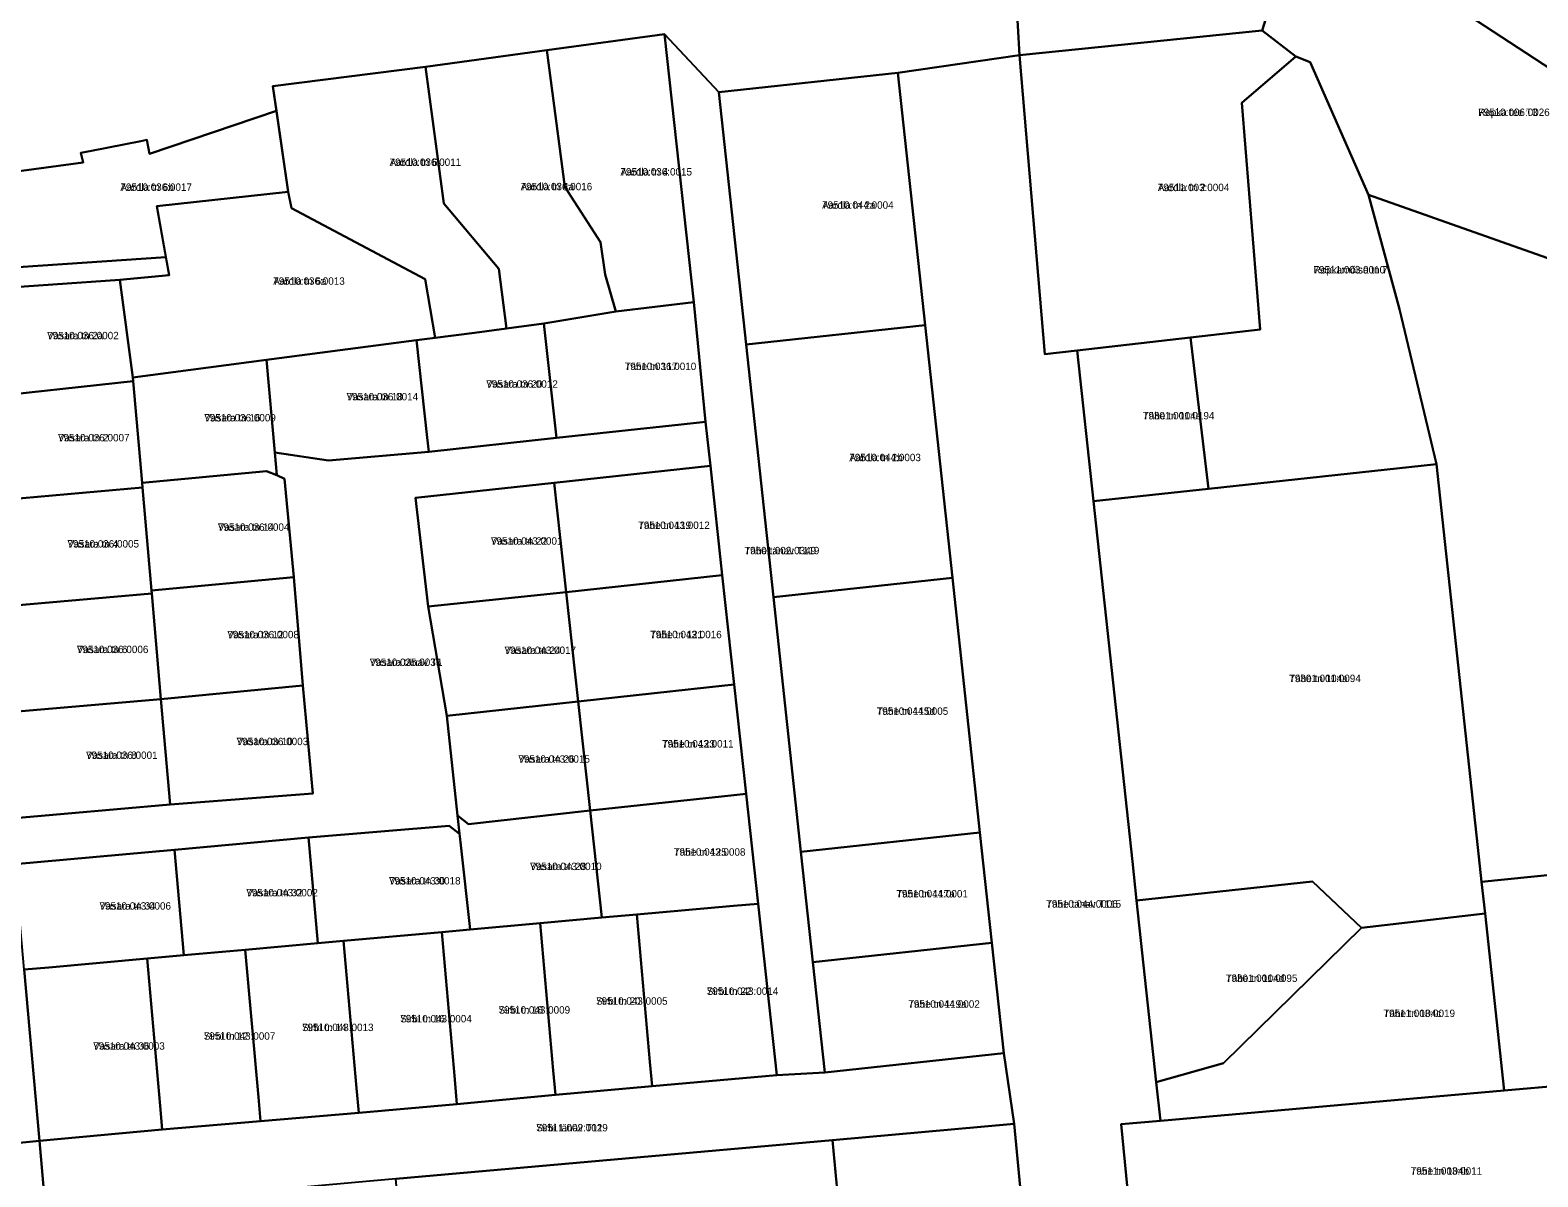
# Model space of a CAD drawing. Extents: x 643847 to 663718, y 6468443 to 6482775.
# Drawn here: x 659596.7 to 659902.3, y 6471374.4 to 6471607 of the extents above; entities that cross this region are included whole.
import ezdxf

# ---------------------------------------------------------------- set-up
doc = ezdxf.new("R2010")
doc.units = 0
for name, color, linetype in [('L_AADRESS', 7, 'Continuous'), ('PIIR', 7, 'Continuous'), ('TUNNUS', 7, 'Continuous')]:
    doc.layers.add(name, color=color, linetype=linetype)

msp = doc.modelspace()

# ---------------------------------------------------------------- linework, layer by layer
at = {"layer": 'PIIR'}
for points in [[(659817.75, 6471799.3), (659833.61, 6471792.85), (659837.53, 6471744.15), (659838.53, 6471692.21), (659839.36, 6471674.7), (659855.96, 6471637.45), (659846.41, 6471606.89), (659797.25, 6471601.92), (659795.21, 6471637.67), (659796.11, 6471658.09), (659796.4, 6471678.1), (659798.71, 6471689.75), (659806.62, 6471693.9), (659821.29, 6471696.22), (659821.65, 6471730.04), (659821.63, 6471758.67), (659819.49, 6471779.17)], [(659795.21, 6471637.67), (659797.25, 6471601.92), (659772.6, 6471598.32), (659736.31, 6471594.4), (659725.24, 6471606.19), (659701.45, 6471602.91), (659676.82, 6471599.52), (659645.89, 6471595.59), (659646.6, 6471590.65), (659620.87, 6471581.91), (659620.31, 6471584.76), (659619.1, 6471584.49), (659609.15, 6471582.53), (659606.98, 6471582.1), (659607.41, 6471580.11), (659580.87, 6471576.54), (659578.73, 6471609.63), (659626.74, 6471615.64), (659641.98, 6471617.51), (659647.44, 6471618.38), (659677.48, 6471622.19), (659712.15, 6471626.9), (659754.93, 6471632.45)], [(659846.41, 6471606.89), (659855.96, 6471637.45), (659873.19, 6471619.88), (659930.09, 6471582.62), (659950.05, 6471577.2), (659951.45, 6471565.89), (659966.86, 6471567.85), (659964.82, 6471541.72), (659932.46, 6471550.82), (659867.98, 6471573.55), (659856.17, 6471600.52), (659853.27, 6471601.63)], [(659701.45, 6471602.91), (659725.24, 6471606.19), (659731.24, 6471551.82), (659715.43, 6471549.92), (659713.23, 6471557.45), (659712.33, 6471563.99), (659705.05, 6471575.23)], [(659734.57, 6471518.62), (659733.58, 6471527.55), (659731.24, 6471551.82), (659725.24, 6471606.19), (659736.31, 6471594.4), (659741.84, 6471543.2), (659747.35, 6471492), (659752.93, 6471440.3), (659755.34, 6471417.93), (659757.75, 6471395.56), (659748.04, 6471395.02), (659744.24, 6471429.79), (659741.81, 6471452.1), (659739.38, 6471474.28), (659736.98, 6471496.45)], [(659846.41, 6471606.89), (659853.27, 6471601.63), (659842.32, 6471592.24), (659846.03, 6471546.27), (659831.88, 6471544.66), (659808.92, 6471542.03), (659802.39, 6471541.28), (659797.25, 6471601.92)], [(659676.82, 6471599.52), (659701.45, 6471602.91), (659705.05, 6471575.23), (659712.33, 6471563.99), (659713.23, 6471557.45), (659715.43, 6471549.92), (659700.8, 6471547.47), (659693.23, 6471546.47), (659691.66, 6471558.56), (659680.51, 6471571.8)], [(659772.6, 6471598.32), (659797.25, 6471601.92), (659802.39, 6471541.28), (659808.92, 6471542.03), (659812.22, 6471511.45), (659820.11, 6471438.38), (659820.96, 6471430.45), (659824.96, 6471393.57), (659825.8, 6471385.79), (659817.82, 6471385.09), (659820.85, 6471354.53), (659824.14, 6471354.79), (659832.72, 6471264.56), (659807.79, 6471262.68), (659803.98, 6471302.78), (659796.16, 6471385.13), (659794.04, 6471399.48), (659791.63, 6471421.84), (659789.22, 6471444.21), (659783.64, 6471495.91), (659778.13, 6471547.12)], [(659856.17, 6471600.52), (659867.98, 6471573.55), (659874.28, 6471550.37), (659881.79, 6471518.95), (659835.58, 6471513.95), (659831.88, 6471544.66), (659846.03, 6471546.27), (659842.32, 6471592.24), (659853.27, 6471601.63)], [(659676.82, 6471599.52), (659680.51, 6471571.8), (659691.66, 6471558.56), (659693.23, 6471546.47), (659686.76, 6471545.62), (659678.76, 6471544.58), (659676.73, 6471556.49), (659649.67, 6471570.9), (659648.96, 6471574.16), (659645.89, 6471595.59)], [(659772.6, 6471598.32), (659778.13, 6471547.12), (659741.84, 6471543.2), (659736.31, 6471594.4)], [(659580.87, 6471576.54), (659607.41, 6471580.11), (659606.98, 6471582.1), (659609.15, 6471582.53), (659619.1, 6471584.49), (659620.31, 6471584.76), (659620.87, 6471581.91), (659646.6, 6471590.65), (659648.96, 6471574.16), (659622.36, 6471571.31), (659624.2, 6471560.96), (659582.22, 6471558.13)], [(659965.79, 6471536.9), (660010.65, 6471539.18), (660217.02, 6471561.69), (660296.35, 6471571.17), (660384.16, 6471579.66), (660385.88, 6471550.23), (660391.97, 6471445.42), (660297.43, 6471441.39), (660298.21, 6471426.96), (660277.53, 6471425.24), (660188.47, 6471417.61), (660128.45, 6471412.44), (659932.57, 6471395.15), (659895.48, 6471391.93), (659891.61, 6471427.79), (659890.91, 6471434.24), (659966.88, 6471441.96), (659984.79, 6471443.78)], [(659648.96, 6471574.16), (659649.67, 6471570.9), (659676.73, 6471556.49), (659678.76, 6471544.58), (659674.99, 6471544.08), (659647.16, 6471540.43), (659644.61, 6471540.1), (659617.49, 6471536.51), (659614.86, 6471556.32), (659624.85, 6471557.31), (659622.36, 6471571.31)], [(659984.79, 6471443.78), (659966.88, 6471441.96), (659890.91, 6471434.24), (659890.36, 6471439.34), (659884.22, 6471496.37), (659881.79, 6471518.95), (659874.28, 6471550.37), (659867.98, 6471573.55), (659932.46, 6471550.82), (659964.82, 6471541.72), (659965.79, 6471536.9)], [(659582.62, 6471554.14), (659587.61, 6471554.48), (659614.86, 6471556.32), (659617.49, 6471536.51), (659617.55, 6471535.79), (659585.24, 6471532.27)], [(659733.59, 6471527.57), (659728.62, 6471527.02), (659703.38, 6471524.27), (659700.8, 6471547.47), (659715.43, 6471549.92), (659731.24, 6471551.82)], [(659677.49, 6471521.46), (659677.16, 6471524.36), (659674.99, 6471544.08), (659678.76, 6471544.58), (659686.76, 6471545.62), (659693.23, 6471546.47), (659700.8, 6471547.47), (659703.38, 6471524.27)], [(659783.64, 6471495.91), (659747.35, 6471492), (659741.84, 6471543.2), (659778.13, 6471547.12)], [(659657.15, 6471519.7), (659646.26, 6471521.32), (659644.61, 6471540.1), (659647.16, 6471540.43), (659674.99, 6471544.08), (659677.16, 6471524.36), (659677.49, 6471521.46)], [(659808.92, 6471542.03), (659831.88, 6471544.66), (659835.58, 6471513.95), (659812.22, 6471511.45)], [(659646.66, 6471516.7), (659644.6, 6471517.52), (659619.37, 6471515.15), (659617.55, 6471535.79), (659617.49, 6471536.51), (659644.61, 6471540.1), (659646.26, 6471521.32)], [(659585.24, 6471532.27), (659617.55, 6471535.79), (659619.37, 6471515.15), (659619.46, 6471514.22), (659592.06, 6471511.8), (659587.13, 6471511.37)], [(659820.11, 6471438.38), (659812.22, 6471511.45), (659835.58, 6471513.95), (659881.79, 6471518.95), (659884.22, 6471496.37), (659890.36, 6471439.34), (659890.91, 6471434.24), (659891.62, 6471427.83), (659866.56, 6471424.91), (659856.64, 6471434.3), (659820.96, 6471430.45)], [(659619.46, 6471514.22), (659619.37, 6471515.15), (659644.6, 6471517.52), (659646.66, 6471516.7), (659648.25, 6471516), (659650.14, 6471496.01), (659621.3, 6471493.35)], [(659736.98, 6471496.45), (659705.35, 6471493), (659702.92, 6471515.17), (659734.57, 6471518.62)], [(659587.13, 6471511.37), (659592.06, 6471511.8), (659619.46, 6471514.22), (659621.3, 6471493.35), (659621.36, 6471492.73), (659593.58, 6471490.27), (659589.07, 6471489.87)], [(659705.35, 6471493), (659677.34, 6471490.06), (659674.78, 6471512.13), (659702.92, 6471515.17)], [(659621.36, 6471492.73), (659621.3, 6471493.35), (659650.14, 6471496.01), (659651.98, 6471474.03), (659623.19, 6471471.27)], [(659739.38, 6471474.28), (659734.42, 6471473.74), (659707.76, 6471470.84), (659705.35, 6471493), (659736.98, 6471496.45)], [(659789.22, 6471444.21), (659752.93, 6471440.3), (659747.35, 6471492), (659783.64, 6471495.91)], [(659589.07, 6471489.87), (659593.58, 6471490.27), (659621.36, 6471492.73), (659623.19, 6471471.27), (659591, 6471468.53)], [(659677.34, 6471490.06), (659705.35, 6471493), (659707.76, 6471470.84), (659681.12, 6471467.92)], [(659651.98, 6471474.03), (659653.98, 6471452.14), (659625.04, 6471449.9), (659623.19, 6471471.27)], [(659741.81, 6471452.1), (659736.84, 6471451.56), (659710.19, 6471448.68), (659707.76, 6471470.84), (659734.42, 6471473.74), (659739.38, 6471474.28)], [(659591, 6471468.53), (659623.19, 6471471.27), (659625.04, 6471449.9), (659592.86, 6471447.07)], [(659683.34, 6471447.72), (659681.12, 6471467.92), (659707.76, 6471470.84), (659710.19, 6471448.68), (659685.54, 6471445.95)], [(659744.24, 6471429.79), (659739.26, 6471429.35), (659719.64, 6471427.6), (659712.56, 6471426.97), (659710.19, 6471448.68), (659736.84, 6471451.56), (659741.81, 6471452.1)], [(659684, 6471441.7), (659683.34, 6471447.72), (659685.54, 6471445.95), (659710.19, 6471448.68), (659712.56, 6471426.97), (659700.05, 6471425.84), (659685.88, 6471424.56)], [(659681.59, 6471445.6), (659683.75, 6471443.94), (659684, 6471441.7), (659685.88, 6471424.56), (659680.14, 6471424.05), (659660.22, 6471422.27), (659655.03, 6471421.8), (659653.34, 6471440.98), (659653.14, 6471443.22)], [(659653.14, 6471443.22), (659653.34, 6471440.98), (659655.03, 6471421.8), (659640.3, 6471420.47), (659627.86, 6471419.35), (659625.96, 6471440.76)], [(659755.34, 6471417.93), (659752.93, 6471440.3), (659789.22, 6471444.21), (659791.63, 6471421.84)], [(659625.96, 6471440.76), (659627.86, 6471419.35), (659620.39, 6471418.67), (659600.46, 6471416.88), (659595.49, 6471416.44), (659593.6, 6471437.84)], [(659824.96, 6471393.57), (659820.96, 6471430.45), (659856.64, 6471434.3), (659866.56, 6471424.91), (659838.61, 6471397.43)], [(659703.15, 6471391.01), (659702.71, 6471395.98), (659700.05, 6471425.84), (659712.56, 6471426.97), (659719.64, 6471427.6), (659722.3, 6471397.74), (659722.75, 6471392.76)], [(659722.75, 6471392.76), (659722.3, 6471397.74), (659719.64, 6471427.6), (659739.26, 6471429.35), (659744.24, 6471429.79), (659748.04, 6471395.02)], [(659825.8, 6471385.79), (659824.96, 6471393.57), (659838.61, 6471397.43), (659866.56, 6471424.91), (659891.62, 6471427.83), (659895.48, 6471391.93), (659857.14, 6471388.56)], [(659662.87, 6471392.39), (659660.22, 6471422.27), (659680.14, 6471424.05), (659682.79, 6471394.17), (659683.21, 6471389.17), (659663.29, 6471387.4)], [(659683.21, 6471389.17), (659682.79, 6471394.17), (659680.14, 6471424.05), (659685.88, 6471424.56), (659700.05, 6471425.84), (659702.71, 6471395.98), (659703.15, 6471391.01)], [(659643.37, 6471385.69), (659642.94, 6471390.58), (659640.3, 6471420.47), (659655.03, 6471421.8), (659660.22, 6471422.27), (659662.87, 6471392.39), (659663.29, 6471387.4)], [(659755.34, 6471417.93), (659791.63, 6471421.84), (659794.04, 6471399.48), (659757.75, 6471395.56)], [(659595.49, 6471416.44), (659600.46, 6471416.88), (659620.39, 6471418.67), (659623.03, 6471388.78), (659623.45, 6471383.99), (659598.59, 6471381.69)], [(659623.45, 6471383.99), (659623.03, 6471388.78), (659620.39, 6471418.67), (659627.86, 6471419.35), (659640.3, 6471420.47), (659642.94, 6471390.58), (659643.37, 6471385.69)], [(659629.59, 6471370.29), (659599.82, 6471367.75), (659598.59, 6471381.69), (659623.45, 6471383.99), (659643.37, 6471385.69), (659663.29, 6471387.4), (659683.21, 6471389.17), (659703.15, 6471391.01), (659722.75, 6471392.76), (659748.04, 6471395.02), (659757.75, 6471395.56), (659794.04, 6471399.48), (659796.16, 6471385.13), (659759.31, 6471381.85), (659670.78, 6471373.97)], [(659860.1, 6471357.95), (659824.14, 6471354.79), (659820.85, 6471354.53), (659817.82, 6471385.09), (659825.8, 6471385.79), (659857.14, 6471388.56), (659895.48, 6471391.93), (659932.57, 6471395.15), (659935.06, 6471364.6)], [(659759.3, 6471381.83), (659796.16, 6471385.13), (659803.98, 6471302.75), (659767.12, 6471299.46)], [(659759.3, 6471381.83), (659761.56, 6471358.02), (659719.57, 6471353.73), (659725.73, 6471289.67), (659767.67, 6471293.7), (659771.91, 6471259.03), (659779.21, 6471192.86), (659781.29, 6471173.88), (659759.52, 6471171.44), (659760.85, 6471158.75), (659691.2, 6471151.9), (659684.41, 6471173.46), (659681.76, 6471217.35), (659678.38, 6471273.27), (659675.48, 6471321.17), (659670.78, 6471373.97)]]:
    msp.add_lwpolyline(points, close=True, dxfattribs=at)
for points in [[(659930.09, 6471582.62), (659873.19, 6471619.88), (659881.22, 6471620.33), (659889.95, 6471620.77), (659916.45, 6471622.16)], [(659582.22, 6471558.13), (659624.2, 6471560.96), (659624.85, 6471557.31), (659614.86, 6471556.32), (659587.61, 6471554.48)], [(659592.86, 6471447.07), (659625.04, 6471449.9), (659653.98, 6471452.14), (659651.98, 6471474.03), (659650.14, 6471496.01), (659648.25, 6471516), (659646.66, 6471516.7), (659646.26, 6471521.32), (659657.15, 6471519.7), (659677.49, 6471521.46), (659703.38, 6471524.27), (659728.62, 6471527.02), (659733.59, 6471527.57), (659734.57, 6471518.62), (659702.92, 6471515.17), (659674.78, 6471512.13), (659677.34, 6471490.06), (659681.12, 6471467.92), (659683.34, 6471447.72), (659683.75, 6471443.94), (659681.59, 6471445.6), (659653.14, 6471443.22), (659625.96, 6471440.76), (659593.6, 6471437.84)], [(659595.49, 6471416.44), (659598.59, 6471381.69), (659574.63, 6471379.32)], [(659574.63, 6471379.32), (659598.59, 6471381.69), (659599.82, 6471367.75), (659602.37, 6471338.73), (659604.45, 6471315.02), (659606.61, 6471290.93), (659608.71, 6471267.23), (659612.89, 6471218.84), (659614.4, 6471190.83), (659616.38, 6471166.47), (659627.82, 6471012.67), (659628.96, 6471011.22), (659609.9, 6471007.88), (659605.06, 6471069.14), (659604.58, 6471075.58), (659601.79, 6471113.01), (659600.59, 6471126.61), (659598.29, 6471152.55), (659596.46, 6471172.5)]]:
    msp.add_lwpolyline(points, dxfattribs=at)

# ---------------------------------------------------------------- texts
at = {"layer": 'L_AADRESS'}
for s, p in [('Ropka tee T3', (659890.21, 6471589.58)), ('Aardla tn 6', (659669.56, 6471579.45)), ('Aardla tn 4', (659716.35, 6471577.5)), ('Aardla tn 6b', (659614.98, 6471574.39)), ('Aardla tn 4a', (659696.12, 6471574.51)), ('Aardla tn 2', (659825.26, 6471574.33)), ('Aardla tn 2a', (659757.22, 6471570.76)), ('Ropkamõisa tn 7', (659856.84, 6471557.63)), ('Aardla tn 6a', (659645.96, 6471555.34)), ('Vasara tn 2a', (659600.13, 6471544.29)), ('Tähe tn 117', (659717.21, 6471538.04)), ('Vasara tn 20', (659689.15, 6471534.46)), ('Vasara tn 18', (659660.83, 6471531.89)), ('Vasara tn 16', (659631.99, 6471527.62)), ('Tähe tn 104e', (659822.25, 6471528.04)), ('Vasara tn 2', (659602.33, 6471523.58)), ('Aardla tn 2b', (659762.74, 6471519.56)), ('Vasara tn 14', (659634.74, 6471505.44)), ('Tähe tn 119', (659719.95, 6471505.81)), ('Vasara tn 4', (659604.25, 6471502.04)), ('Vasara tn 22', (659690.09, 6471502.62)), ('Tähe tänav T119', (659741.5, 6471500.68)), ('Vasara tn 12', (659636.66, 6471483.64)), ('Tähe tn 121', (659722.37, 6471483.65)), ('Vasara tn 6', (659606.15, 6471480.63)), ('Vasara tänav T1', (659665.52, 6471478.03)), ('Vasara tn 24', (659692.85, 6471480.46)), ('Tähe tn 104a', (659851.92, 6471474.75)), ('Tähe tn 115d', (659768.29, 6471468.11)), ('Vasara tn 10', (659638.54, 6471461.96)), ('Tähe tn 123', (659724.78, 6471461.48)), ('Vasara tn 8', (659608.02, 6471459.17)), ('Vasara tn 26', (659695.65, 6471458.4)), ('Tähe tn 125', (659727.18, 6471439.54)), ('Vasara tn 28', (659698.03, 6471436.62)), ('Vasara tn 30', (659669.43, 6471433.7)), ('Vasara tn 32', (659640.5, 6471431.29)), ('Tähe tn 117a', (659772.28, 6471431.07)), ('Tähe tänav T115', (659802.66, 6471429)), ('Vasara tn 34', (659610.73, 6471428.6)), ('Tähe tn 104d', (659839.07, 6471413.94)), ('Sirbi tn 22', (659733.84, 6471411.31)), ('Sirbi tn 18', (659691.64, 6471407.51)), ('Sirbi tn 20', (659711.4, 6471409.31)), ('Tähe tn 119a', (659774.69, 6471408.7)), ('Sirbi tn 16', (659671.71, 6471405.72)), ('Tähe tn 104c', (659871.02, 6471406.81)), ('Sirbi tn 12', (659631.88, 6471402.21)), ('Sirbi tn 14', (659651.79, 6471403.96)), ('Vasara tn 36', (659609.47, 6471400.19)), ('Sirbi tänav T11', (659699.27, 6471383.62)), ('Tähe tn 104b', (659876.53, 6471374.84))]:
    msp.add_text(s, height=1.5, dxfattribs=at).set_placement(p)
at = {"layer": 'TUNNUS'}
for s, p in [('79510:006:0026', (659890.21, 6471589.58)), ('79510:036:0011', (659669.56, 6471579.45)), ('79510:036:0015', (659716.35, 6471577.5)), ('79510:036:0017', (659614.98, 6471574.39)), ('79510:036:0016', (659696.12, 6471574.51)), ('79511:003:0004', (659825.26, 6471574.33)), ('79510:044:0004', (659757.22, 6471570.76)), ('79511:003:0010', (659856.84, 6471557.63)), ('79510:036:0013', (659645.96, 6471555.34)), ('79510:036:0002', (659600.13, 6471544.29)), ('79510:036:0010', (659717.21, 6471538.04)), ('79510:036:0012', (659689.15, 6471534.46)), ('79510:036:0014', (659660.83, 6471531.89)), ('79510:036:0009', (659631.99, 6471527.62)), ('79301:001:0194', (659822.25, 6471528.04)), ('79510:036:0007', (659602.33, 6471523.58)), ('79510:044:0003', (659762.74, 6471519.56)), ('79510:036:0004', (659634.74, 6471505.44)), ('79510:043:0012', (659719.95, 6471505.81)), ('79510:036:0005', (659604.25, 6471502.04)), ('79510:043:0001', (659690.09, 6471502.62)), ('79501:002:0349', (659741.5, 6471500.68)), ('79510:036:0008', (659636.66, 6471483.64)), ('79510:043:0016', (659722.37, 6471483.65)), ('79510:036:0006', (659606.15, 6471480.63)), ('79510:035:0035', (659665.52, 6471478.03)), ('79510:043:0017', (659692.85, 6471480.46)), ('79301:001:0094', (659851.92, 6471474.75)), ('79510:044:0005', (659768.29, 6471468.11)), ('79510:036:0003', (659638.54, 6471461.96)), ('79510:043:0011', (659724.78, 6471461.48)), ('79510:036:0001', (659608.02, 6471459.17)), ('79510:043:0015', (659695.65, 6471458.4)), ('79510:043:0008', (659727.18, 6471439.54)), ('79510:043:0010', (659698.03, 6471436.62)), ('79510:043:0018', (659669.43, 6471433.7)), ('79510:043:0002', (659640.5, 6471431.29)), ('79510:044:0001', (659772.28, 6471431.07)), ('79510:044:0006', (659802.66, 6471429)), ('79510:043:0006', (659610.73, 6471428.6)), ('79301:001:0095', (659839.07, 6471413.94)), ('79510:043:0014', (659733.84, 6471411.31)), ('79510:043:0009', (659691.64, 6471407.51)), ('79510:043:0005', (659711.4, 6471409.31)), ('79510:044:0002', (659774.69, 6471408.7)), ('79510:043:0004', (659671.71, 6471405.72)), ('79511:003:0019', (659871.02, 6471406.81)), ('79510:043:0007', (659631.88, 6471402.21)), ('79510:043:0013', (659651.79, 6471403.96)), ('79510:043:0003', (659609.47, 6471400.19)), ('79511:002:0029', (659699.27, 6471383.62)), ('79511:003:0011', (659876.53, 6471374.84))]:
    msp.add_text(s, height=1.5, dxfattribs=at).set_placement(p)

doc.saveas('drawing.dxf')
